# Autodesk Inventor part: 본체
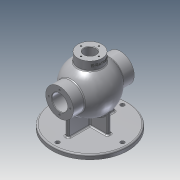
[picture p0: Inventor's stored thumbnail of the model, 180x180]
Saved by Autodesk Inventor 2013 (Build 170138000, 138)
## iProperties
Created: 2020-08
Part Number: 본체
Material: 알루미늄 6061
Document SubType Name: Modeling
Designer: 19
Density: 2.71 g/cm^3
Mass: 1759.18 g
Surface Area: 1342.42 cm^2
Volume: 649.143 cm^3
Author: 19
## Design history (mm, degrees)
sketch "스케치1"
  geometry: L1 (17.289, -50.101)-(-17.289, 50.101); A1 r 53 centre (0, 0) between (17.289, -50.101) and (-17.289, 50.101); 1 further point
  constraints: 2 end point, 2 point on circle, 1 centre point, 1 coincident, 1 midpoint
  dimensions: "d0" = 53 radius of A1
revolve "회전1" sketch "스케치1" stored, may be unused: angle "d1" = 90 deg
node "작업 평면1"
sketch "스케치2"
  geometry: C1 r 31 at (0, 0); 1 further point
  constraints: 1 centre point, 1 coincident
  dimensions: "d3" = 62 diameter of C1
extrude "돌출1" join sketch "스케치2" stored distance "d4" = 10; taper "d5" = 0 deg
sketch "스케치3"
  geometry: C1 r 31 at (0, 0) reference; C2 r 17.5 at (0, 0)
  constraints: 1 centre point, 1 coincident
  dimensions: "d6" = 35 diameter of C2
extrude "돌출2" cut sketch "스케치3" stored distance "d8" = 10; taper "d9" = 0 deg
sketch "스케치4" dims "d11" = 48
  geometry: C1 r 17.5 at (0, 0) reference; C2 r 31 at (0, 0) reference; 2 further points
  constraints: 3 coincident, 2 vertical alignment, 2 other
hole "구멍1" sketch "스케치4" at (0, 24) diameter "d12" = 3.242; stored, may be unused: countersink angle "d16" = 90 deg, drill point angle "d18" = 118 deg; dims "d13" = 12, "d14" = 4, "d15" = 2, "d17" = 15
sketch "스케치5"
  geometry: L1 (-68, 31)-(-42.988, 31) reference; L2 (42.988, 31)-(68, 31) reference; L3 (68, 31)-(68, 25.621) reference; L4 (68, 25.621)-(53, 25.621) reference; L5 (53, 25.621)-(52.026, 24) reference; L6 (52.026, 24)-(53, 22.379) reference; L7 (53, 22.379)-(68, 22.379) reference; L8 (68, 22.379)-(68, 17.5) reference; L9 (68, 17.5)-(-68, 17.5) reference; L10 (-68, 17.5)-(-68, 22.379) reference; L11 (-68, 22.379)-(-53, 22.379) reference; L12 (-53, 22.379)-(-52.026, 24) reference; L13 (-52.026, 24)-(-53, 25.621) reference; L14 (-53, 25.621)-(-68, 25.621) reference; L15 (-68, 25.621)-(-68, 31) reference; L16 (-42.988, -31)-(-68, -31) reference; L17 (-68, -31)-(-68, -25.621) reference; L18 (-68, -25.621)-(-53, -25.621) reference; L19 (-53, -25.621)-(-52.026, -24) reference; L20 (-52.026, -24)-(-53, -22.379) reference; L21 (-53, -22.379)-(-68, -22.379) reference; L22 (-68, -22.379)-(-68, -17.5) reference; L23 (-68, -17.5)-(68, -17.5) reference; L24 (68, -17.5)-(68, -22.379) reference; L25 (68, -22.379)-(53, -22.379) reference; L26 (53, -22.379)-(52.026, -24) reference; L27 (52.026, -24)-(53, -25.621) reference; L28 (53, -25.621)-(68, -25.621) reference; L29 (68, -25.621)-(68, -31) reference; L30 (68, -31)-(42.988, -31) reference; L31 (19.526, -38.311)-(-19.526, 38.311); A1 r 53 centre (0, 0) between (42.988, 31) and (0, 53) reference; A2 r 53 centre (0, 0) between (0, 53) and (-42.988, 31) reference; A3 r 53 centre (0, 0) between (-42.988, -31) and (0, -53) reference; A4 r 53 centre (0, 0) between (0, -53) and (42.988, -31) reference; A5 r 43 centre (0, 0) between (19.526, -38.311) and (-19.526, 38.311); 1 further point
  constraints: 2 end point, 2 point on circle, 1 centre point, 1 coincident, 1 midpoint
  dimensions: "d22" = 43 radius of A5
revolve "회전2" sketch "스케치5" stored, may be unused: angle "d23" = 90 deg
sketch "스케치6"
  geometry: L1 (-68, 31)-(-42.988, 31) reference; L2 (42.988, 31)-(68, 31) reference; L3 (68, 31)-(68, 25.621) reference; L4 (68, 25.621)-(53, 25.621) reference; L5 (53, 25.621)-(52.026, 24) reference; L6 (52.026, 24)-(53, 22.379) reference; L7 (53, 22.379)-(68, 22.379) reference; L8 (68, 22.379)-(68, 17.5) reference; L9 (68, 17.5)-(39.278, 17.5) reference; L10 (-39.278, 17.5)-(-68, 17.5) reference; L11 (-68, 17.5)-(-68, 22.379) reference; L12 (-68, 22.379)-(-53, 22.379) reference; L13 (-53, 22.379)-(-52.026, 24) reference; L14 (-52.026, 24)-(-53, 25.621) reference; L15 (-53, 25.621)-(-68, 25.621) reference; L16 (-68, 25.621)-(-68, 31) reference; L17 (-42.988, -31)-(-68, -31) reference; L18 (-68, -31)-(-68, -25.621) reference; L19 (-68, -25.621)-(-53, -25.621) reference; L20 (-53, -25.621)-(-52.026, -24) reference; L21 (-52.026, -24)-(-53, -22.379) reference; L22 (-53, -22.379)-(-68, -22.379) reference; L23 (-68, -22.379)-(-68, -17.5) reference; L24 (-68, -17.5)-(-39.278, -17.5) reference; L25 (39.278, -17.5)-(68, -17.5) reference; L26 (68, -17.5)-(68, -22.379) reference; L27 (68, -22.379)-(53, -22.379) reference; L28 (53, -22.379)-(52.026, -24) reference; L29 (52.026, -24)-(53, -25.621) reference; L30 (53, -25.621)-(68, -25.621) reference; L31 (68, -25.621)-(68, -31) reference; L32 (68, -31)-(42.988, -31) reference; L33 (-68, -17.5)-(-68, 17.5) reference; L34 (68, 17.5)-(68, -17.5) reference; L35 (-68, 0)-(68, 0); L36 (-52, 0)-(-52, 18.5); L37 (-52, 18.5)-(-50.25, 18.5); L38 (-50.25, 18.5)-(-50.25, 0); A1 r 53 centre (0, 0) between (42.988, 31) and (0, 53) reference; A2 r 53 centre (0, 0) between (0, 53) and (-42.988, 31) reference; A3 r 43 centre (0, 0) between (39.278, 17.5) and (0, 43) reference; A4 r 43 centre (0, 0) between (0, 43) and (-39.278, 17.5) reference; A5 r 43 centre (0, 0) between (-39.278, -17.5) and (0, -43) reference; A6 r 43 centre (0, 0) between (0, -43) and (39.278, -17.5) reference; A7 r 53 centre (0, 0) between (-42.988, -31) and (0, -53) reference; A8 r 53 centre (0, 0) between (0, -53) and (42.988, -31) reference; 1 further point
  constraints: 8 end point, 2 midpoint, 2 perpendicular, 2 point on line, 1 parallel
  dimensions: "d24" = 37 diameter of L37 L35; "d26" = 1.75 distance of L36.end L37.end; "d27" = 16 distance between parallel lines of L36 L33
revolve "회전3" sketch "스케치6" stored, may be unused: angle "d28" = 90 deg
node "작업 평면2"
sketch "스케치7"
  geometry: C1 r 27 at (0, 0); 1 further point
  constraints: 1 centre point, 1 coincident
  dimensions: "d30" = 54 diameter of C1
extrude "돌출3" join sketch "스케치7" stored distance "d31" = 10; taper "d32" = 0 deg
sketch "스케치8"
  geometry: C1 r 27 at (0, 0) reference; C2 r 13 at (0, 0)
  constraints: 1 centre point, 1 coincident
  dimensions: "d33" = 26 diameter of C2
extrude "돌출4" cut sketch "스케치8" stored distance "d34" = 10; taper "d35" = 0 deg
sketch "스케치9" dims "d36" = 40
  geometry: C1 r 13 at (0, 0) reference; C2 r 27 at (0, 0) reference; 2 further points
  constraints: 3 coincident, 2 vertical alignment, 2 other
hole "구멍2" sketch "스케치9" at (0, 20) diameter "d37" = 3.242; stored, may be unused: countersink angle "d41" = 90 deg, drill point angle "d43" = 118 deg; dims "d38" = 12, "d39" = 4, "d40" = 2, "d42" = 15
node "작업 평면3"
sketch "스케치10"
  geometry: C1 r 85 at (0, 0); 1 further point
  constraints: 1 centre point, 1 coincident
  dimensions: "d48" = 170 diameter of C1
extrude "돌출5" join sketch "스케치10" distance "d49" = 10; taper "d50" = 0 deg
sketch "스케치11"
  geometry: L1 (-31, 42.988)-(31, 42.988) reference; L2 (31, -42.988)-(-31, -42.988) reference; L3 (31, 68)-(-31, 68) reference; L4 (-31, 42.988)-(31, 42.988) reference; L5 (31, -68)-(-31, -68) reference; L6 (31, -42.988)-(-31, -42.988) reference; L7 (-43, 4)-(43, 4); L8 (43, 4)-(43, -4); L9 (43, -4)-(-43, -4); L10 (-43, -4)-(-43, 4); C1 r 85 at (0, 0) reference; C2 r 85 at (0, 0) reference; C3 r 27 at (0, 0) reference; C4 r 85 at (0, 0) reference; 5 further points
  constraints: 8 end point, 2 midpoint, 2 parallel, 1 horizontal, 1 horizontal alignment, 1 perpendicular, 1 vertical alignment, 1 other
  dimensions: "d51" = 86 distance of L8.end L9.end; "d53" = 8 distance of L9.end L7.start
extrude "돌출6" join sketch "스케치11" stored distance "d54" = 10; taper "d55" = 0 deg
sketch "스케치12"
  geometry: L1 (-4, 52)-(4, 52); L2 (4, 52)-(4, -52); L3 (4, -52)-(-4, -52); L4 (-4, -52)-(-4, 52); C1 r 85 at (0, 0) reference; 2 further points
  constraints: 8 end point, 2 midpoint, 2 parallel, 1 horizontal, 1 horizontal alignment, 1 perpendicular, 1 vertical alignment
  dimensions: "d56" = 104 distance of L1.end L2.end; "d58" = 8 distance of L1.start L1.end
extrude "돌출7" join sketch "스케치12" stored distance "d59" = 10; taper "d60" = 0 deg
node "작업 평면4"
chamfer "모따기1" distance "d77" = 1; stored, may be unused: second distance "d78" = 2, angle "d79" = 45 deg
fillet "모깎기1" dims "d80" = 3
fillet "모깎기2" dims "d81" = 3
fillet "모깎기3" dims "d82" = 3
fillet "모깎기4" dims "d83" = 3
fillet "모깎기5" dims "d84" = 3
node "작업 평면5"
sketch "스케치15"
  geometry: L1 (-27, 65)-(27, 65) reference; L2 (-27, 47.286)-(27, 47.286) reference; L3 (-27, 65)-(-27, 47.286) reference; L4 (27, 65)-(27, 47.286) reference; 2 further points
  constraints: 1 other
  dimensions: "d86" = 9 distance from line of point (0, 56) L1; "d87" = 27 distance from line of point (0, 56) L3
feature "엠보싱2" sketch "스케치15" dims "d88" = 0.5, "d89" = 0
sketch "스케치16" dims "d91" = 145
  geometry: C1 r 82 at (0, 0) reference; 2 further points
  constraints: 2 vertical alignment, 1 coincident, 2 other
hole "구멍4" sketch "스케치16" at (0, 72.5) diameter "d92" = 9; stored, may be unused: countersink angle "d96" = 90 deg, drill point angle "d98" = 118 deg; dims "d93" = 12, "d94" = 4, "d95" = 2, "d97" = 15
node "솔리드1"
mirror "대칭1"
pattern_circular "원형 패턴1" dims angle "d20" = 360 deg
mirror "대칭2"
pattern_circular "원형 패턴2" dims angle "d45" = 360 deg
pattern_circular "원형 패턴4" dims angle "d100" = 360 deg
node "투영된 루프1"
node "투영된 루프2"
node "투영된 루프3"
node "투영된 루프4"
node "절단 모서리 투영1"
node "절단 모서리 투영2"
node "절단 모서리 투영3"
node "절단 모서리 투영4"
other parameters: "d2" = -68, "d29" = 65, "d47" = -85, "d61" = -134.5, "d85" = -37.25
